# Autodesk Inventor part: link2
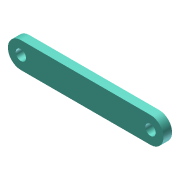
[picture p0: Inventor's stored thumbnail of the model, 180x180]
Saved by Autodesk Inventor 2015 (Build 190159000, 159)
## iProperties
Created: 2020-09
Part Number: link2
Material: 一般
Document SubType Name: Modeling
Designer: 徐冠倫
Mass: 49.8066 g
Surface Area: 146.578 cm^2
Volume: 49.8066 cm^3
Density: 1 g/cm^3
Appearance: 預設
Author: 徐冠倫
Author: IANNIAN
Title: D:\Desktop\OCW-Computer-Aided Engineering Drawing\OCW_Topic 06：組合圖與機構模擬(進階)\6-1_Flexibility\Mechanical Gripper(piston)\Mechanical Gripper(STP)\link2.stp
Creation Date: 2020-09-04
Sending System: Autodesk Inventor 2020
Preprocessor: ST-DEVELOPER v18
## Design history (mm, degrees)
node "link21"
body "Solid1"
node "Base1"
